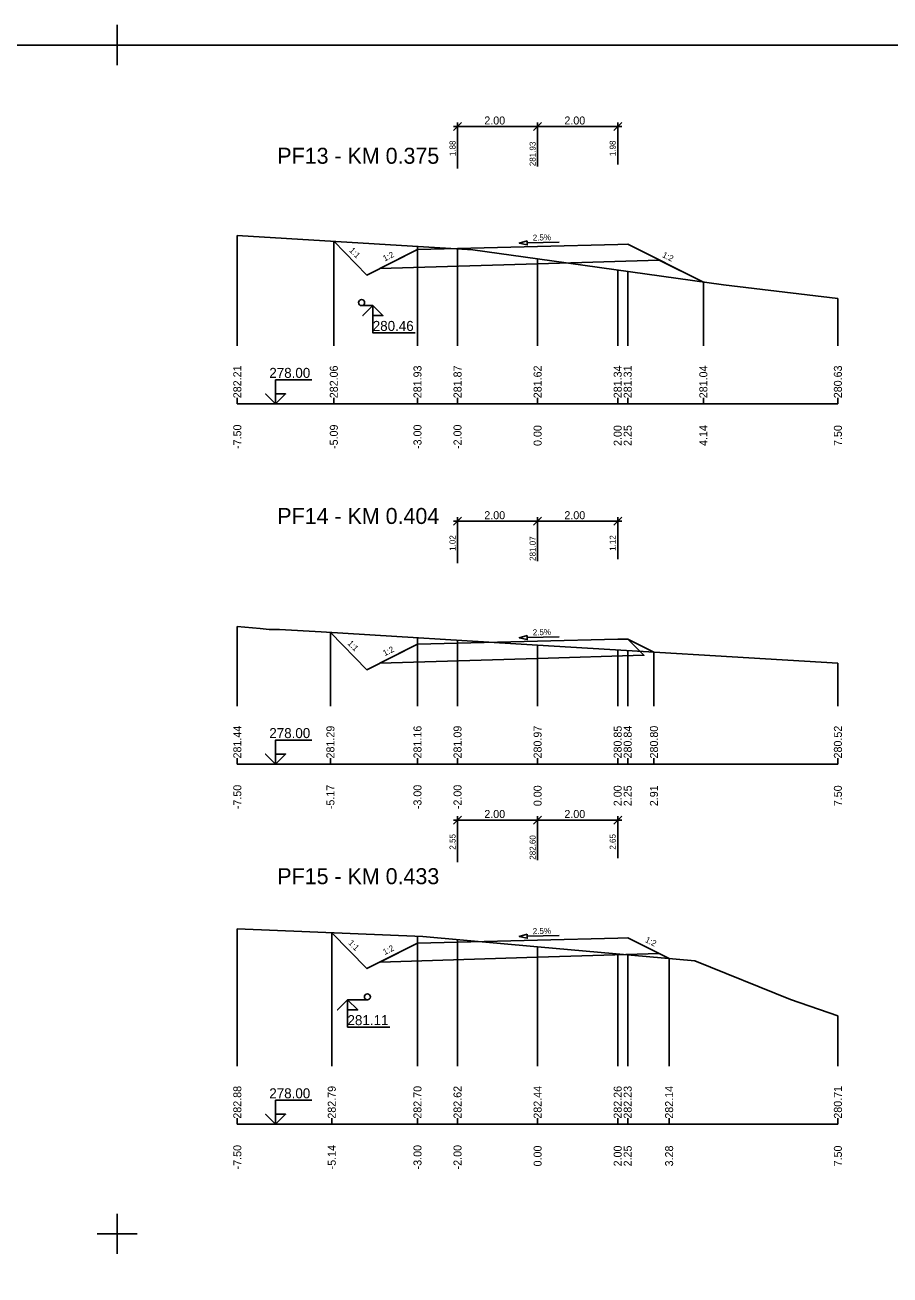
# Model space of a CAD drawing. Extents: x -5 to 1895, y -2 to 602.
# Drawn here: x 817 to 1033, y 289.4 to 601.7 of the extents above; entities that cross this region are included whole.
import ezdxf

# ---------------------------------------------------------------- set-up
doc = ezdxf.new("R2010")
doc.units = 0
for name, color, linetype in [('KOTA', 7, 'Continuous'), ('KOTA_DELKY', 7, 'Continuous'), ('KOTA_DELKY_CONT', 7, 'Continuous'), ('KRIZENI', 7, 'Continuous'), ('NS_TELESO_VOZOVKY', 7, 'Continuous'), ('NS_V_PF', 7, 'Continuous'), ('REZY_PF_PUVODNI', 7, 'Continuous'), ('SESTAVY_REZU_PF', 7, 'Continuous'), ('SKLON', 7, 'Continuous'), ('SVK', 7, 'Continuous')]:
    doc.layers.add(name, color=color, linetype=linetype)

msp = doc.modelspace()

# ---------------------------------------------------------------- linework, layer by layer
for p, q in [((840, 601.67), (840, 591.67)), ((840, 601.67), (840, 591.67)), ((840, 601.67), (840, 591.67)), ((840, 601.67), (840, 591.67)), ((840, 601.67), (840, 591.67)), ((840, 601.67), (840, 591.67)), ((840, 601.67), (840, 591.67)), ((840, 601.67), (840, 591.67)), ((840, 601.67), (840, 591.67)), ((840, 601.67), (840, 591.67)), ((840, 601.67), (840, 591.67)), ((840, 601.67), (840, 591.67)), ((840, 601.67), (840, 591.67)), ((840, 601.67), (840, 591.67)), ((840, 601.67), (840, 591.67)), ((840, 601.67), (840, 591.67)), ((840, 601.67), (840, 591.67)), ((840, 601.67), (840, 591.67)), ((840, 601.67), (840, 591.67)), ((840, 601.67), (840, 591.67)), ((840, 601.67), (840, 591.67)), ((840, 601.67), (840, 591.67)), ((840, 601.67), (840, 591.67)), ((840, 601.67), (840, 591.67)), ((840, 601.67), (840, 591.67)), ((840, 601.67), (840, 591.67)), ((840, 601.67), (840, 591.67)), ((840, 601.67), (840, 591.67)), ((840, 601.67), (840, 591.67)), ((840, 601.67), (840, 591.67)), ((840, 601.67), (840, 591.67)), ((840, 601.67), (840, 591.67)), ((840, 601.67), (840, 591.67)), ((840, 601.67), (840, 591.67)), ((840, 601.67), (840, 591.67)), ((840, 601.67), (840, 591.67)), ((840, 601.67), (840, 591.67)), ((840, 601.67), (840, 591.67)), ((840, 601.67), (840, 591.67)), ((840, 601.67), (840, 591.67)), ((840, 601.67), (840, 591.67)), ((840, 601.67), (840, 591.67)), ((840, 601.67), (840, 591.67)), ((840, 601.67), (840, 591.67)), ((840, 601.67), (840, 591.67)), ((840, 601.67), (840, 591.67)), ((840, 601.67), (840, 591.67)), ((840, 601.67), (840, 591.67)), ((840, 601.67), (840, 591.67)), ((840, 601.67), (840, 591.67)), ((840, 601.67), (840, 591.67)), ((840, 601.67), (840, 591.67)), ((840, 601.67), (840, 591.67)), ((840, 601.67), (840, 591.67)), ((845, 596.67), (835, 596.67)), ((845, 596.67), (835, 596.67)), ((845, 596.67), (835, 596.67)), ((845, 596.67), (835, 596.67)), ((845, 596.67), (835, 596.67)), ((845, 596.67), (835, 596.67)), ((845, 596.67), (835, 596.67)), ((845, 596.67), (835, 596.67)), ((845, 596.67), (835, 596.67)), ((845, 596.67), (835, 596.67)), ((845, 596.67), (835, 596.67)), ((845, 596.67), (835, 596.67)), ((845, 596.67), (835, 596.67)), ((845, 596.67), (835, 596.67)), ((845, 596.67), (835, 596.67)), ((845, 596.67), (835, 596.67)), ((845, 596.67), (835, 596.67)), ((845, 596.67), (835, 596.67)), ((845, 596.67), (835, 596.67)), ((845, 596.67), (835, 596.67)), ((845, 596.67), (835, 596.67)), ((845, 596.67), (835, 596.67)), ((845, 596.67), (835, 596.67)), ((845, 596.67), (835, 596.67)), ((845, 596.67), (835, 596.67)), ((845, 596.67), (835, 596.67)), ((845, 596.67), (835, 596.67)), ((845, 596.67), (835, 596.67)), ((845, 596.67), (835, 596.67)), ((845, 596.67), (835, 596.67)), ((845, 596.67), (835, 596.67)), ((845, 596.67), (835, 596.67)), ((845, 596.67), (835, 596.67)), ((845, 596.67), (835, 596.67)), ((845, 596.67), (835, 596.67)), ((845, 596.67), (835, 596.67)), ((845, 596.67), (835, 596.67)), ((845, 596.67), (835, 596.67)), ((845, 596.67), (835, 596.67)), ((845, 596.67), (835, 596.67)), ((845, 596.67), (835, 596.67)), ((845, 596.67), (835, 596.67)), ((845, 596.67), (835, 596.67)), ((845, 596.67), (835, 596.67)), ((845, 596.67), (835, 596.67)), ((845, 596.67), (835, 596.67)), ((845, 596.67), (835, 596.67)), ((845, 596.67), (835, 596.67)), ((845, 596.67), (835, 596.67)), ((845, 596.67), (835, 596.67)), ((845, 596.67), (835, 596.67)), ((845, 596.67), (835, 596.67)), ((845, 596.67), (835, 596.67)), ((845, 596.67), (835, 596.67)), ((840, 304.67), (840, 294.67)), ((840, 304.67), (840, 294.67)), ((840, 304.67), (840, 294.67)), ((840, 304.67), (840, 294.67)), ((840, 304.67), (840, 294.67)), ((840, 304.67), (840, 294.67)), ((840, 304.67), (840, 294.67)), ((840, 304.67), (840, 294.67)), ((840, 304.67), (840, 294.67)), ((840, 304.67), (840, 294.67)), ((840, 304.67), (840, 294.67)), ((840, 304.67), (840, 294.67)), ((840, 304.67), (840, 294.67)), ((840, 304.67), (840, 294.67)), ((840, 304.67), (840, 294.67)), ((840, 304.67), (840, 294.67)), ((840, 304.67), (840, 294.67)), ((840, 304.67), (840, 294.67)), ((840, 304.67), (840, 294.67)), ((840, 304.67), (840, 294.67)), ((840, 304.67), (840, 294.67)), ((840, 304.67), (840, 294.67)), ((840, 304.67), (840, 294.67)), ((840, 304.67), (840, 294.67)), ((840, 304.67), (840, 294.67)), ((840, 304.67), (840, 294.67)), ((840, 304.67), (840, 294.67)), ((840, 304.67), (840, 294.67)), ((840, 304.67), (840, 294.67)), ((840, 304.67), (840, 294.67)), ((840, 304.67), (840, 294.67)), ((840, 304.67), (840, 294.67)), ((840, 304.67), (840, 294.67)), ((840, 304.67), (840, 294.67)), ((840, 304.67), (840, 294.67)), ((840, 304.67), (840, 294.67)), ((840, 304.67), (840, 294.67)), ((840, 304.67), (840, 294.67)), ((840, 304.67), (840, 294.67)), ((840, 304.67), (840, 294.67)), ((840, 304.67), (840, 294.67)), ((840, 304.67), (840, 294.67)), ((840, 304.67), (840, 294.67)), ((840, 304.67), (840, 294.67)), ((840, 304.67), (840, 294.67)), ((840, 304.67), (840, 294.67)), ((840, 304.67), (840, 294.67)), ((840, 304.67), (840, 294.67)), ((840, 304.67), (840, 294.67)), ((840, 304.67), (840, 294.67)), ((840, 304.67), (840, 294.67)), ((840, 304.67), (840, 294.67)), ((840, 304.67), (840, 294.67)), ((840, 304.67), (840, 294.67)), ((845, 299.67), (835, 299.67)), ((845, 299.67), (835, 299.67)), ((845, 299.67), (835, 299.67)), ((845, 299.67), (835, 299.67)), ((845, 299.67), (835, 299.67)), ((845, 299.67), (835, 299.67)), ((845, 299.67), (835, 299.67)), ((845, 299.67), (835, 299.67)), ((845, 299.67), (835, 299.67)), ((845, 299.67), (835, 299.67)), ((845, 299.67), (835, 299.67)), ((845, 299.67), (835, 299.67)), ((845, 299.67), (835, 299.67)), ((845, 299.67), (835, 299.67)), ((845, 299.67), (835, 299.67)), ((845, 299.67), (835, 299.67)), ((845, 299.67), (835, 299.67)), ((845, 299.67), (835, 299.67)), ((845, 299.67), (835, 299.67)), ((845, 299.67), (835, 299.67)), ((845, 299.67), (835, 299.67)), ((845, 299.67), (835, 299.67)), ((845, 299.67), (835, 299.67)), ((845, 299.67), (835, 299.67)), ((845, 299.67), (835, 299.67)), ((845, 299.67), (835, 299.67)), ((845, 299.67), (835, 299.67)), ((845, 299.67), (835, 299.67)), ((845, 299.67), (835, 299.67)), ((845, 299.67), (835, 299.67)), ((845, 299.67), (835, 299.67)), ((845, 299.67), (835, 299.67)), ((845, 299.67), (835, 299.67)), ((845, 299.67), (835, 299.67)), ((845, 299.67), (835, 299.67)), ((845, 299.67), (835, 299.67)), ((845, 299.67), (835, 299.67)), ((845, 299.67), (835, 299.67)), ((845, 299.67), (835, 299.67)), ((845, 299.67), (835, 299.67)), ((845, 299.67), (835, 299.67)), ((845, 299.67), (835, 299.67)), ((845, 299.67), (835, 299.67)), ((845, 299.67), (835, 299.67)), ((845, 299.67), (835, 299.67)), ((845, 299.67), (835, 299.67)), ((845, 299.67), (835, 299.67)), ((845, 299.67), (835, 299.67)), ((845, 299.67), (835, 299.67)), ((845, 299.67), (835, 299.67)), ((845, 299.67), (835, 299.67)), ((845, 299.67), (835, 299.67)), ((845, 299.67), (835, 299.67)), ((845, 299.67), (835, 299.67))]:
    msp.add_line(p, q)
msp.add_lwpolyline([(0, 596.67), (1890, 596.67), (1890, 2.67), (0, 2.67)], close=True)
at = {"layer": 'KOTA'}
for points in [[(901.05, 531.55), (903.87, 531.55)], [(903.87, 531.55), (901.37, 529.05), (903.87, 531.55), (903.87, 524.73), (914.41, 524.73)], [(903.87, 531.55), (906.37, 529.05), (903.87, 529.05), (903.87, 531.55)], [(903.87, 531.55), (906.37, 529.05), (903.87, 529.05)], [(879.57, 507), (877.07, 509.5), (879.57, 507), (879.57, 513), (888.57, 513)], [(879.57, 507), (882.07, 509.5), (879.57, 509.5), (879.57, 507)], [(879.57, 507), (882.07, 509.5), (879.57, 509.5)], [(879.57, 417), (877.07, 419.5), (879.57, 417), (879.57, 423), (888.57, 423)], [(879.57, 417), (882.07, 419.5), (879.57, 419.5), (879.57, 417)], [(879.57, 417), (882.07, 419.5), (879.57, 419.5)], [(897.56, 358.1), (895.06, 355.6), (897.56, 358.1), (897.56, 351.28), (908.11, 351.28)], [(902.48, 358.1), (897.56, 358.1)], [(897.56, 358.1), (900.06, 355.6), (897.56, 355.6), (897.56, 358.1)], [(897.56, 358.1), (900.06, 355.6), (897.56, 355.6)], [(879.57, 327), (877.07, 329.5), (879.57, 327), (879.57, 333), (888.57, 333)], [(879.57, 327), (882.07, 329.5), (879.57, 329.5), (879.57, 327)], [(879.57, 327), (882.07, 329.5), (879.57, 329.5)]]:
    msp.add_lwpolyline(points, dxfattribs=at)
at = {"layer": 'KOTA_DELKY'}
for points in [[(924, 575.31), (926, 577.31)], [(924, 576.31), (946, 576.31)], [(925, 565.81), (925, 577.31)], [(944, 575.31), (946, 577.31)], [(944, 575.31), (946, 577.31)], [(944, 576.31), (966, 576.31)], [(945, 566.31), (945, 577.31)], [(945, 566.31), (945, 577.31)], [(964, 575.31), (966, 577.31)], [(965, 566.81), (965, 577.31)], [(924, 476.69), (926, 478.69)], [(925, 467.19), (925, 478.69)], [(944, 476.69), (946, 478.69)], [(944, 476.69), (946, 478.69)], [(945, 467.69), (945, 478.69)], [(945, 467.69), (945, 478.69)], [(964, 476.69), (966, 478.69)], [(965, 468.19), (965, 478.69)], [(924, 477.69), (946, 477.69)], [(944, 477.69), (966, 477.69)], [(924, 402.03), (926, 404.03)], [(924, 403.03), (946, 403.03)], [(925, 392.53), (925, 404.03)], [(944, 402.03), (946, 404.03)], [(944, 402.03), (946, 404.03)], [(944, 403.03), (966, 403.03)], [(945, 393.03), (945, 404.03)], [(945, 393.03), (945, 404.03)], [(964, 402.03), (966, 404.03)], [(965, 393.53), (965, 404.03)]]:
    msp.add_lwpolyline(points, dxfattribs=at)
at = {"layer": 'KRIZENI'}
for centre in [(901.05, 532.3), (902.48, 358.85)]:
    msp.add_circle(centre, 0.75, dxfattribs=at)
at = {"layer": 'NS_TELESO_VOZOVKY'}
for points in [[(945, 546.31), (965, 546.81), (967.5, 546.87), (986.4, 537.42), (975.4, 542.92), (945, 542.01), (905.62, 540.83), (915, 545.56), (925, 545.81), (945, 546.31)], [(945, 447.69), (965, 448.19), (967.5, 448.25), (971.57, 444.19), (945, 443.39), (905.62, 442.21), (915, 446.94), (925, 447.19), (945, 447.69)], [(945, 373.03), (965, 373.53), (967.5, 373.6), (977.85, 368.42), (975.4, 369.64), (945, 368.73), (905.62, 367.55), (915, 372.28), (925, 372.53), (945, 373.03)]]:
    msp.add_lwpolyline(points, dxfattribs=at)
at = {"layer": 'NS_V_PF'}
for points in [[(894.1, 547.62), (902.37, 539.19), (915, 545.56), (925, 545.81), (945, 546.31), (965, 546.81), (967.5, 546.87), (986.4, 537.42)], [(893.25, 449.87), (902.37, 440.57), (915, 446.94), (925, 447.19), (945, 447.69), (965, 448.19), (967.5, 448.25), (974.06, 444.98)], [(893.59, 374.86), (902.37, 365.91), (915, 372.28), (925, 372.53), (945, 373.03), (965, 373.53), (967.5, 373.6), (977.85, 368.42)]]:
    msp.add_lwpolyline(points, dxfattribs=at)
at = {"layer": 'REZY_PF_PUVODNI'}
for points in [[(870, 549.09), (928.82, 545.49), (945, 543.22), (945, 543.22), (991.39, 536.72), (1020, 533.31)], [(870, 451.4), (875.71, 450.87), (877.99, 450.67), (878.2, 450.66), (880.51, 450.61), (890.92, 450.01), (945, 446.74), (945, 446.74), (1020, 442.19)], [(870, 375.83), (916.31, 373.94), (945, 371.36), (984.31, 367.84), (1008.15, 358.2), (1020, 354.14)]]:
    msp.add_lwpolyline(points, dxfattribs=at)
at = {"layer": 'SESTAVY_REZU_PF'}
for points in [[(870, 507), (1020, 507)], [(870, 417), (1020, 417)], [(870, 327), (1020, 327)]]:
    msp.add_lwpolyline(points, dxfattribs=at)
at = {"layer": 'SKLON'}
for points in [[(942.39, 547.74), (940.4, 547.19), (942.41, 546.74)], [(942.39, 449.13), (940.4, 448.58), (942.41, 448.13)], [(942.39, 374.47), (940.4, 373.92), (942.41, 373.47)]]:
    msp.add_lwpolyline(points, close=True, dxfattribs=at)
for points in [[(942.39, 547.74), (940.4, 547.19), (942.41, 546.74), (942.39, 547.74)], [(942.4, 547.24), (950.4, 547.44)], [(942.39, 449.13), (940.4, 448.58), (942.41, 448.13), (942.39, 449.13)], [(942.4, 448.63), (950.4, 448.83)], [(942.39, 374.47), (940.4, 373.92), (942.41, 373.47), (942.39, 374.47)], [(942.4, 373.97), (950.4, 374.17)]]:
    msp.add_lwpolyline(points, dxfattribs=at)
at = {"layer": 'SVK'}
for points in [[(870, 521.5), (870, 549.09)], [(894.1, 521.5), (894.1, 547.62)], [(915, 521.5), (915, 546.34)], [(925, 521.5), (925, 545.72)], [(945, 521.5), (945, 543.22)], [(965, 521.5), (965, 540.42)], [(967.5, 521.5), (967.5, 540.07)], [(986.4, 521.5), (986.4, 537.42)], [(1020, 521.5), (1020, 533.31)], [(870, 507), (870, 508.5)], [(894.1, 507), (894.1, 508.5)], [(915, 507), (915, 508.5)], [(925, 507), (925, 508.5)], [(945, 507), (945, 508.5)], [(965, 507), (965, 508.5)], [(967.5, 507), (967.5, 508.5)], [(986.4, 507), (986.4, 508.5)], [(1020, 507), (1020, 508.5)], [(870, 431.5), (870, 451.4)], [(893.25, 431.5), (893.25, 449.87)], [(915, 431.5), (915, 448.55)], [(925, 431.5), (925, 447.95)], [(945, 431.5), (945, 446.74)], [(965, 431.5), (965, 445.53)], [(967.5, 431.5), (967.5, 445.37)], [(974.06, 431.5), (974.06, 444.98)], [(1020, 431.5), (1020, 442.19)], [(870, 417), (870, 418.5)], [(893.25, 417), (893.25, 418.5)], [(915, 417), (915, 418.5)], [(925, 417), (925, 418.5)], [(945, 417), (945, 418.5)], [(965, 417), (965, 418.5)], [(967.5, 417), (967.5, 418.5)], [(974.06, 417), (974.06, 418.5)], [(1020, 417), (1020, 418.5)], [(870, 341.5), (870, 375.83)], [(893.59, 341.5), (893.59, 374.86)], [(915, 341.5), (915, 373.99)], [(925, 341.5), (925, 373.16)], [(945, 341.5), (945, 371.36)], [(965, 341.5), (965, 369.57)], [(967.5, 341.5), (967.5, 369.35)], [(977.85, 341.5), (977.85, 368.42)], [(1020, 341.5), (1020, 354.14)], [(870, 327), (870, 328.5)], [(893.59, 327), (893.59, 328.5)], [(915, 327), (915, 328.5)], [(925, 327), (925, 328.5)], [(945, 327), (945, 328.5)], [(965, 327), (965, 328.5)], [(967.5, 327), (967.5, 328.5)], [(977.85, 327), (977.85, 328.5)], [(1020, 327), (1020, 328.5)]]:
    msp.add_lwpolyline(points, dxfattribs=at)

# ---------------------------------------------------------------- texts
at = {"layer": 'KOTA'}
for s, p in [('280.46', (903.83, 525.23)), ('278.00', (877.99, 513.5)), ('278.00', (877.99, 423.5)), ('281.11', (897.52, 351.78)), ('278.00', (877.99, 333.5))]:
    msp.add_text(s, height=2.5, dxfattribs=at).set_placement(p)
at = {"layer": 'KOTA_DELKY'}
for p in [(931.69, 576.81), (951.69, 576.81), (931.69, 478.19), (951.69, 478.19), (931.69, 403.53), (951.69, 403.53)]:
    msp.add_text('2.00', height=2, dxfattribs=at).set_placement(p)
at = {"layer": 'KOTA_DELKY_CONT'}
for s, p in [('1.88', (924.5, 568.9)), ('281.93', (944.5, 566.39)), ('1.98', (964.5, 568.9)), ('1.02', (924.5, 470.28)), ('281.07', (944.5, 467.77)), ('1.12', (964.5, 470.28)), ('2.55', (924.5, 395.62)), ('282.60', (944.5, 393.11)), ('2.65', (964.5, 395.62))]:
    msp.add_text(s, height=1.5, rotation=90, dxfattribs=at).set_placement(p)
at = {"layer": 'SESTAVY_REZU_PF'}
for s, p in [('PF13 - KM 0.375', (880, 567)), ('PF14 - KM 0.404', (880, 477)), ('PF15 - KM 0.433', (880, 387))]:
    msp.add_text(s, height=4, dxfattribs=at).set_placement(p)
at = {"layer": 'SKLON'}
for s, rotation, p in [('2.5%', 1.4321, (943.8, 547.78)), ('1:1', 314.4213, (897.85, 545.23)), ('1:2', 26.7649, (906.82, 542.56)), ('1:2', 333.4349, (975.99, 543.75)), ('2.5%', 1.4321, (943.8, 449.16)), ('1:1', 314.4213, (897.42, 447.05)), ('1:2', 26.7649, (906.82, 443.94)), ('2.5%', 1.4321, (943.8, 374.5)), ('1:1', 314.4213, (897.59, 372.21)), ('1:2', 26.7649, (906.82, 369.28)), ('1:2', 333.4349, (971.71, 372.61))]:
    msp.add_text(s, height=1.5, rotation=rotation, dxfattribs=at).set_placement(p)
at = {"layer": 'SVK'}
for s, p in [(' 282.21', (871, 507.67)), (' 282.06', (895.1, 507.67)), (' 281.93', (916, 507.67)), (' 281.87', (926, 507.67)), (' 281.62', (946, 507.67)), (' 281.34', (966, 507.67)), (' 281.31', (968.5, 507.67)), (' 281.04', (987.4, 507.67)), (' 280.63', (1021, 507.67)), (' -7.50', (871, 495)), (' -5.09', (895.1, 495)), (' -3.00', (916, 495)), (' -2.00', (926, 495)), ('  0.00', (946, 495)), ('  2.00', (966, 495)), ('  2.25', (968.5, 495)), ('  4.14', (987.4, 495)), ('  7.50', (1021, 495)), (' 281.44', (871, 417.67)), (' 281.29', (894.25, 417.67)), (' 281.16', (916, 417.67)), (' 281.09', (926, 417.67)), (' 280.97', (946, 417.67)), (' 280.85', (966, 417.67)), (' 280.84', (968.5, 417.67)), (' 280.80', (975.06, 417.67)), (' 280.52', (1021, 417.67)), (' -7.50', (871, 405)), (' -5.17', (894.25, 405)), (' -3.00', (916, 405)), (' -2.00', (926, 405)), ('  0.00', (946, 405)), ('  2.00', (966, 405)), ('  2.25', (968.5, 405)), ('  2.91', (975.06, 405)), ('  7.50', (1021, 405)), (' 282.88', (871, 327.67)), (' 282.79', (894.59, 327.67)), (' 282.70', (916, 327.67)), (' 282.62', (926, 327.67)), (' 282.44', (946, 327.67)), (' 282.26', (966, 327.67)), (' 282.23', (968.5, 327.67)), (' 282.14', (978.85, 327.67)), (' 280.71', (1021, 327.67)), (' -7.50', (871, 315)), (' -5.14', (894.59, 315)), (' -3.00', (916, 315)), (' -2.00', (926, 315)), ('  0.00', (946, 315)), ('  2.00', (966, 315)), ('  2.25', (968.5, 315)), ('  3.28', (978.85, 315)), ('  7.50', (1021, 315))]:
    msp.add_text(s, height=2, rotation=90, dxfattribs=at).set_placement(p)

doc.saveas('drawing.dxf')
